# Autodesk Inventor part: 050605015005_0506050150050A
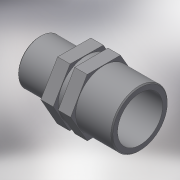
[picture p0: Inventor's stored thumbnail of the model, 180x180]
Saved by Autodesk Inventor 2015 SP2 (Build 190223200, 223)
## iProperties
Created: 2017-05
Part Number: 050605015005_0506050150050A
Material: Generic
Description: PLASSON REDUCING NIPPLE 1.1/2"-1/2"
Document SubType Name: Modeling
Designer: KIM
Density: 1 g/cm^3
Appearance: Default
Author: KIM
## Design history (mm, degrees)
derived "050605.ipt"
feature "Solid1::050605.ipt"
tag "TaggingFeature1"
body "Solid1"
other parameters: "d0" = 54, "d1" = 47.803, "d5" = 21, "d6" = 5.4, "d8" = 0.54, "d12" = 0, "d14" = 20.955, "d15" = 16.764, "d16" = 38.2424, "d17" = 16, "d18" = 2.7, "d21" = 0, "H_" = 54, "R_" = 47.803, "l_" = 21, "R_1" = 20.955, "l_1" = 16
